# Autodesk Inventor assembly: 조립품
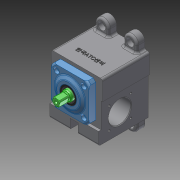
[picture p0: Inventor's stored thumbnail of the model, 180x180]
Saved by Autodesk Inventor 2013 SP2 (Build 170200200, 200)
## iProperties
Created: 2024-11
Part Number: 조립품
Document SubType Name: Assembly
Designer: a
Author: a
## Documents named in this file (6)
- C:\Users\a\Desktop\741104V1017\조립품.iam
- C:\Users\a\Desktop\741104V1017\본체.ipt
- C:\Users\a\Desktop\741104V1017\깊음 홈 볼 베어링 6202.ipt
- C:\Users\a\Desktop\741104V1017\피니언 축.ipt
- C:\Users\a\Desktop\741104V1017\커버.ipt
- C:\Users\a\Desktop\741104V1017\오일 실 15 25 4.ipt
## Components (1 placed, 1 different names)
1. 피니언 축:1
